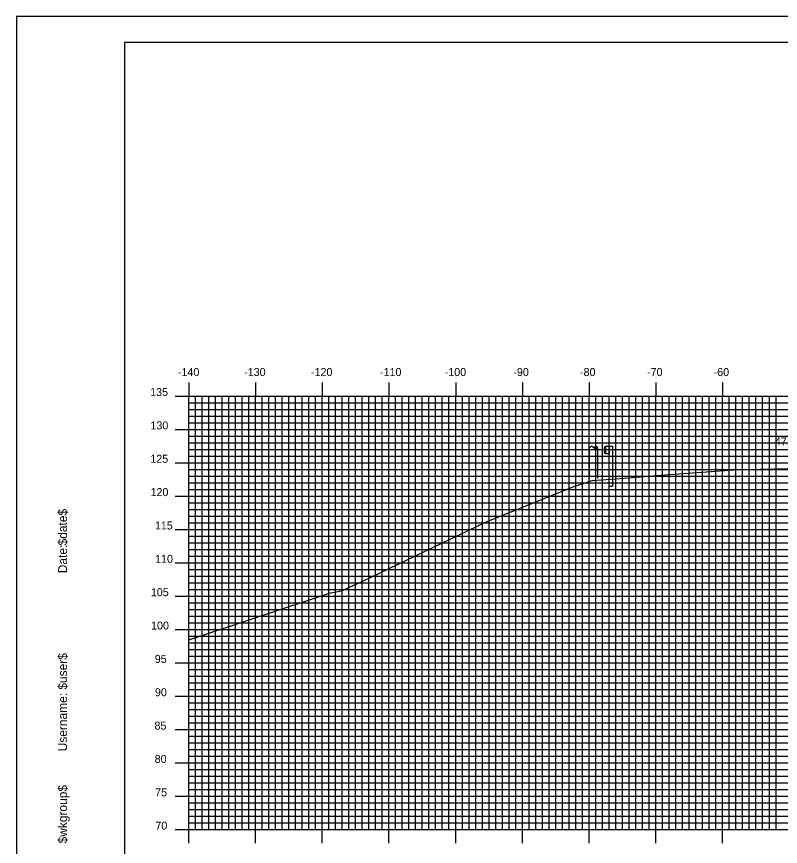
# Model space of a CAD drawing. Extents: x 858684 to 859027, y 364765 to 364985.
# Drawn here: x 858684.1 to 858798.5, y 364860.8 to 364985.2 of the extents above; entities that cross this region are included whole.
import ezdxf

# ---------------------------------------------------------------- set-up
doc = ezdxf.new("R2010")
doc.units = 0
for name, color, linetype in [('BORDER', 7, 'Continuous'), ('D_Text_Standard', 7, 'Continuous'), ('H_V ANNOTATION', 7, 'Continuous'), ('M_Guardrail', 7, 'Continuous'), ('M_Roadway_Centerline', 7, 'Continuous'), ('M_Utilities_Pole_StreetLight', 7, 'Continuous'), ('MAJOR', 7, 'Continuous'), ('MINOR', 7, 'Continuous'), ('PLOT BOUNDARY', 7, 'Continuous'), ('S_Roadway_Centerline', 7, 'Continuous')]:
    doc.layers.add(name, color=color, linetype=linetype)

msp = doc.modelspace()

# ---------------------------------------------------------------- linework, layer by layer
at = {"layer": 'BORDER'}
msp.add_lwpolyline([(858700.25, 364771.3), (859020.25, 364771.3), (859020.25, 364981.3), (858700.25, 364981.3)], close=True, dxfattribs=at)
at = {"layer": 'M_Guardrail'}
for p, q in [((858772.26, 364920.71), (858772.12, 364920.61)), ((858772.12, 364920.47), (858772.31, 364920.33)), ((858772.31, 364920.11), (858772.12, 364919.98)), ((858772.36, 364920.73), (858772.28, 364920.72)), ((858772.34, 364920.27), (858772.34, 364920.18)), ((858772.36, 364920.81), (858772.85, 364920.81)), ((858772.36, 364919.64), (858772.36, 364920.81)), ((858772.85, 364920.81), (858773.34, 364920.81)), ((858772.85, 364920.81), (858772.85, 364919.64)), ((858773.34, 364920.81), (858773.34, 364914.81)), ((858772.12, 364919.83), (858772.26, 364919.73)), ((858772.28, 364919.73), (858772.36, 364919.71)), ((858772.85, 364919.64), (858772.36, 364919.64)), ((858772.85, 364914.81), (858772.85, 364919.64)), ((858772.85, 364914.81), (858773.34, 364914.81))]:
    msp.add_line(p, q, dxfattribs=at)
for centre, major_axis, start_param, end_param in [((858772.17, 364920.54), (-0.0877, 0), 5.323254, 7.243116), ((858772.28, 364920.68), (-0.0417, 0), 4.886922, 5.323254), ((858772.27, 364920.27), (0.0789, 0), 0, 0.959931), ((858772.27, 364920.18), (0.0789, 0), 5.323254, 6.283185), ((858772.17, 364919.91), (-0.0877, 0), 5.323254, 7.243116), ((858772.28, 364919.77), (-0.0417, 0), 0.959931, 1.396263)]:
    msp.add_ellipse(centre, major_axis=major_axis, ratio=0.995501, start_param=start_param, end_param=end_param, dxfattribs=at)
at = {"layer": 'M_Utilities_Pole_StreetLight'}
for p, q in [((858769.9, 364920.59), (858770.06, 364920.7)), ((858769.9, 364915.97), (858769.9, 364920.59)), ((858770.37, 364920.7), (858770.53, 364920.59)), ((858770.68, 364920.7), (858770.53, 364920.59)), ((858770.53, 364920.59), (858770.68, 364920.48)), ((858771.15, 364920.59), (858771, 364920.7)), ((858771, 364920.48), (858771.15, 364920.59)), ((858771.15, 364915.97), (858771.15, 364920.59))]:
    msp.add_line(p, q, dxfattribs=at)
for centre, start, end in [((858770.22, 364920.48), 90, 125.2644), ((858770.22, 364920.48), 54.7356, 90), ((858770.84, 364920.48), 90, 125.2644), ((858770.84, 364920.7), 234.7356, 270), ((858770.84, 364920.48), 54.7356, 90), ((858770.84, 364920.7), 270, 305.2644)]:
    msp.add_arc(centre, 0.271, start, end, dxfattribs=at)
at = {"layer": 'MAJOR'}
for p, q in [((858709.85, 364930.31), (858709.85, 364928.3)), ((858719.85, 364930.31), (858719.85, 364928.3)), ((858729.85, 364930.31), (858729.85, 364928.3)), ((858739.85, 364930.31), (858739.85, 364928.3)), ((858749.85, 364930.31), (858749.85, 364928.3)), ((858759.85, 364930.31), (858759.85, 364928.3)), ((858769.85, 364930.31), (858769.85, 364928.3)), ((858779.85, 364930.31), (858779.85, 364928.3)), ((858789.85, 364930.31), (858789.85, 364928.3)), ((858707.84, 364928.3), (858709.85, 364928.3)), ((858709.85, 364928.3), (858989.85, 364928.3)), ((858709.85, 364863.3), (858709.85, 364928.3)), ((858709.85, 364863.3), (858709.85, 364928.3)), ((858709.85, 364928.3), (858989.85, 364928.3)), ((858719.85, 364863.3), (858719.85, 364928.3)), ((858729.85, 364863.3), (858729.85, 364928.3)), ((858739.85, 364863.3), (858739.85, 364928.3)), ((858749.85, 364863.3), (858749.85, 364928.3)), ((858759.85, 364863.3), (858759.85, 364928.3)), ((858769.85, 364863.3), (858769.85, 364928.3)), ((858779.85, 364863.3), (858779.85, 364928.3)), ((858789.85, 364863.3), (858789.85, 364928.3)), ((858707.84, 364923.3), (858709.85, 364923.3)), ((858709.85, 364923.3), (858989.85, 364923.3)), ((858707.84, 364918.3), (858709.85, 364918.3)), ((858709.85, 364918.3), (858989.85, 364918.3)), ((858707.84, 364913.3), (858709.85, 364913.3)), ((858709.85, 364913.3), (858989.85, 364913.3)), ((858707.84, 364908.3), (858709.85, 364908.3)), ((858709.85, 364908.3), (858989.85, 364908.3)), ((858707.84, 364903.3), (858709.85, 364903.3)), ((858709.85, 364903.3), (858989.85, 364903.3)), ((858707.84, 364898.3), (858709.85, 364898.3)), ((858709.85, 364898.3), (858989.85, 364898.3)), ((858707.84, 364893.3), (858709.85, 364893.3)), ((858709.85, 364893.3), (858989.85, 364893.3)), ((858707.84, 364888.3), (858709.85, 364888.3)), ((858709.85, 364888.3), (858989.85, 364888.3)), ((858707.84, 364883.3), (858709.85, 364883.3)), ((858709.85, 364883.3), (858989.85, 364883.3)), ((858707.84, 364878.3), (858709.85, 364878.3)), ((858709.85, 364878.3), (858989.85, 364878.3)), ((858707.84, 364873.3), (858709.85, 364873.3)), ((858709.85, 364873.3), (858989.85, 364873.3)), ((858707.84, 364868.3), (858709.85, 364868.3)), ((858709.85, 364868.3), (858989.85, 364868.3)), ((858707.84, 364863.3), (858709.85, 364863.3)), ((858709.85, 364863.3), (858989.85, 364863.3)), ((858709.85, 364863.3), (858989.85, 364863.3)), ((858709.85, 364861.3), (858709.85, 364863.3)), ((858719.85, 364861.3), (858719.85, 364863.3)), ((858729.85, 364861.3), (858729.85, 364863.3)), ((858739.85, 364861.3), (858739.85, 364863.3)), ((858749.85, 364861.3), (858749.85, 364863.3)), ((858759.85, 364861.3), (858759.85, 364863.3)), ((858769.85, 364861.3), (858769.85, 364863.3)), ((858779.85, 364861.3), (858779.85, 364863.3)), ((858789.85, 364861.3), (858789.85, 364863.3))]:
    msp.add_line(p, q, dxfattribs=at)
at = {"layer": 'MINOR'}
for p, q in [((858710.85, 364863.3), (858710.85, 364928.3)), ((858711.85, 364863.3), (858711.85, 364928.3)), ((858712.85, 364863.3), (858712.85, 364928.3)), ((858713.85, 364863.3), (858713.85, 364928.3)), ((858714.85, 364863.3), (858714.85, 364928.3)), ((858715.85, 364863.3), (858715.85, 364928.3)), ((858716.85, 364863.3), (858716.85, 364928.3)), ((858717.85, 364863.3), (858717.85, 364928.3)), ((858718.85, 364863.3), (858718.85, 364928.3)), ((858720.85, 364863.3), (858720.85, 364928.3)), ((858721.85, 364863.3), (858721.85, 364928.3)), ((858722.85, 364863.3), (858722.85, 364928.3)), ((858723.85, 364863.3), (858723.85, 364928.3)), ((858724.85, 364863.3), (858724.85, 364928.3)), ((858725.85, 364863.3), (858725.85, 364928.3)), ((858726.85, 364863.3), (858726.85, 364928.3)), ((858727.85, 364863.3), (858727.85, 364928.3)), ((858728.85, 364863.3), (858728.85, 364928.3)), ((858730.85, 364863.3), (858730.85, 364928.3)), ((858731.85, 364863.3), (858731.85, 364928.3)), ((858732.85, 364863.3), (858732.85, 364928.3)), ((858733.85, 364863.3), (858733.85, 364928.3)), ((858734.85, 364863.3), (858734.85, 364928.3)), ((858735.85, 364863.3), (858735.85, 364928.3)), ((858736.85, 364863.3), (858736.85, 364928.3)), ((858737.85, 364863.3), (858737.85, 364928.3)), ((858738.85, 364863.3), (858738.85, 364928.3)), ((858740.85, 364863.3), (858740.85, 364928.3)), ((858741.85, 364863.3), (858741.85, 364928.3)), ((858742.85, 364863.3), (858742.85, 364928.3)), ((858743.85, 364863.3), (858743.85, 364928.3)), ((858744.85, 364863.3), (858744.85, 364928.3)), ((858745.85, 364863.3), (858745.85, 364928.3)), ((858746.85, 364863.3), (858746.85, 364928.3)), ((858747.85, 364863.3), (858747.85, 364928.3)), ((858748.85, 364863.3), (858748.85, 364928.3)), ((858750.85, 364863.3), (858750.85, 364928.3)), ((858751.85, 364863.3), (858751.85, 364928.3)), ((858752.85, 364863.3), (858752.85, 364928.3)), ((858753.85, 364863.3), (858753.85, 364928.3)), ((858754.85, 364863.3), (858754.85, 364928.3)), ((858755.85, 364863.3), (858755.85, 364928.3)), ((858756.85, 364863.3), (858756.85, 364928.3)), ((858757.85, 364863.3), (858757.85, 364928.3)), ((858758.85, 364863.3), (858758.85, 364928.3)), ((858760.85, 364863.3), (858760.85, 364928.3)), ((858761.85, 364863.3), (858761.85, 364928.3)), ((858762.85, 364863.3), (858762.85, 364928.3)), ((858763.85, 364863.3), (858763.85, 364928.3)), ((858764.85, 364863.3), (858764.85, 364928.3)), ((858765.85, 364863.3), (858765.85, 364928.3)), ((858766.85, 364863.3), (858766.85, 364928.3)), ((858767.85, 364863.3), (858767.85, 364928.3)), ((858768.85, 364863.3), (858768.85, 364928.3)), ((858770.85, 364863.3), (858770.85, 364928.3)), ((858771.85, 364863.3), (858771.85, 364928.3)), ((858772.85, 364863.3), (858772.85, 364928.3)), ((858773.85, 364863.3), (858773.85, 364928.3)), ((858774.85, 364863.3), (858774.85, 364928.3)), ((858775.85, 364863.3), (858775.85, 364928.3)), ((858776.85, 364863.3), (858776.85, 364928.3)), ((858777.85, 364863.3), (858777.85, 364928.3)), ((858778.85, 364863.3), (858778.85, 364928.3)), ((858780.85, 364863.3), (858780.85, 364928.3)), ((858781.85, 364863.3), (858781.85, 364928.3)), ((858782.85, 364863.3), (858782.85, 364928.3)), ((858783.85, 364863.3), (858783.85, 364928.3)), ((858784.85, 364863.3), (858784.85, 364928.3)), ((858785.85, 364863.3), (858785.85, 364928.3)), ((858786.85, 364863.3), (858786.85, 364928.3)), ((858787.85, 364863.3), (858787.85, 364928.3)), ((858788.85, 364863.3), (858788.85, 364928.3)), ((858790.85, 364863.3), (858790.85, 364928.3)), ((858791.85, 364863.3), (858791.85, 364928.3)), ((858792.85, 364863.3), (858792.85, 364928.3)), ((858793.85, 364863.3), (858793.85, 364928.3)), ((858794.85, 364863.3), (858794.85, 364928.3)), ((858795.85, 364863.3), (858795.85, 364928.3)), ((858796.85, 364863.3), (858796.85, 364928.3)), ((858797.85, 364863.3), (858797.85, 364928.3)), ((858709.85, 364927.3), (858989.85, 364927.3)), ((858709.85, 364927.3), (858711.85, 364927.3)), ((858709.85, 364926.3), (858989.85, 364926.3)), ((858709.85, 364926.3), (858711.85, 364926.3)), ((858709.85, 364925.3), (858989.85, 364925.3)), ((858709.85, 364925.3), (858711.85, 364925.3)), ((858709.85, 364924.3), (858989.85, 364924.3)), ((858709.85, 364924.3), (858711.85, 364924.3)), ((858709.85, 364922.3), (858989.85, 364922.3)), ((858709.85, 364922.3), (858711.85, 364922.3)), ((858709.85, 364921.3), (858989.85, 364921.3)), ((858709.85, 364921.3), (858711.85, 364921.3)), ((858709.85, 364920.3), (858989.85, 364920.3)), ((858709.85, 364920.3), (858711.85, 364920.3)), ((858709.85, 364919.3), (858989.85, 364919.3)), ((858709.85, 364919.3), (858711.85, 364919.3)), ((858709.85, 364917.3), (858989.85, 364917.3)), ((858709.85, 364917.3), (858711.85, 364917.3)), ((858709.85, 364916.3), (858989.85, 364916.3)), ((858709.85, 364916.3), (858711.85, 364916.3)), ((858709.85, 364915.3), (858989.85, 364915.3)), ((858709.85, 364915.3), (858711.85, 364915.3)), ((858709.85, 364914.3), (858989.85, 364914.3)), ((858709.85, 364914.3), (858711.85, 364914.3)), ((858709.85, 364912.3), (858989.85, 364912.3)), ((858709.85, 364912.3), (858711.85, 364912.3)), ((858709.85, 364911.3), (858989.85, 364911.3)), ((858709.85, 364911.3), (858711.85, 364911.3)), ((858709.85, 364910.3), (858989.85, 364910.3)), ((858709.85, 364910.3), (858711.85, 364910.3)), ((858709.85, 364909.3), (858989.85, 364909.3)), ((858709.85, 364909.3), (858711.85, 364909.3)), ((858709.85, 364907.3), (858989.85, 364907.3)), ((858709.85, 364907.3), (858711.85, 364907.3)), ((858709.85, 364906.3), (858989.85, 364906.3)), ((858709.85, 364906.3), (858711.85, 364906.3)), ((858709.85, 364905.3), (858989.85, 364905.3)), ((858709.85, 364905.3), (858711.85, 364905.3)), ((858709.85, 364904.3), (858989.85, 364904.3)), ((858709.85, 364904.3), (858711.85, 364904.3)), ((858709.85, 364902.3), (858989.85, 364902.3)), ((858709.85, 364902.3), (858711.85, 364902.3)), ((858709.85, 364901.3), (858989.85, 364901.3)), ((858709.85, 364901.3), (858711.85, 364901.3)), ((858709.85, 364900.3), (858989.85, 364900.3)), ((858709.85, 364900.3), (858711.85, 364900.3)), ((858709.85, 364899.3), (858989.85, 364899.3)), ((858709.85, 364899.3), (858711.85, 364899.3)), ((858709.85, 364897.3), (858989.85, 364897.3)), ((858709.85, 364897.3), (858711.85, 364897.3)), ((858709.85, 364896.3), (858989.85, 364896.3)), ((858709.85, 364896.3), (858711.85, 364896.3)), ((858709.85, 364895.3), (858989.85, 364895.3)), ((858709.85, 364895.3), (858711.85, 364895.3)), ((858709.85, 364894.3), (858989.85, 364894.3)), ((858709.85, 364894.3), (858711.85, 364894.3)), ((858709.85, 364892.3), (858989.85, 364892.3)), ((858709.85, 364892.3), (858711.85, 364892.3)), ((858709.85, 364891.3), (858989.85, 364891.3)), ((858709.85, 364891.3), (858711.85, 364891.3)), ((858709.85, 364890.3), (858989.85, 364890.3)), ((858709.85, 364890.3), (858711.85, 364890.3)), ((858709.85, 364889.3), (858989.85, 364889.3)), ((858709.85, 364889.3), (858711.85, 364889.3)), ((858709.85, 364887.3), (858989.85, 364887.3)), ((858709.85, 364887.3), (858711.85, 364887.3)), ((858709.85, 364886.3), (858989.85, 364886.3)), ((858709.85, 364886.3), (858711.85, 364886.3)), ((858709.85, 364885.3), (858989.85, 364885.3)), ((858709.85, 364885.3), (858711.85, 364885.3)), ((858709.85, 364884.3), (858989.85, 364884.3)), ((858709.85, 364884.3), (858711.85, 364884.3)), ((858709.85, 364882.3), (858989.85, 364882.3)), ((858709.85, 364882.3), (858711.85, 364882.3)), ((858709.85, 364881.3), (858989.85, 364881.3)), ((858709.85, 364881.3), (858711.85, 364881.3)), ((858709.85, 364880.3), (858989.85, 364880.3)), ((858709.85, 364880.3), (858711.85, 364880.3)), ((858709.85, 364879.3), (858989.85, 364879.3)), ((858709.85, 364879.3), (858711.85, 364879.3)), ((858709.85, 364877.3), (858989.85, 364877.3)), ((858709.85, 364877.3), (858711.85, 364877.3)), ((858709.85, 364876.3), (858989.85, 364876.3)), ((858709.85, 364876.3), (858711.85, 364876.3)), ((858709.85, 364875.3), (858989.85, 364875.3)), ((858709.85, 364875.3), (858711.85, 364875.3)), ((858709.85, 364874.3), (858989.85, 364874.3)), ((858709.85, 364874.3), (858711.85, 364874.3)), ((858709.85, 364872.3), (858989.85, 364872.3)), ((858709.85, 364872.3), (858711.85, 364872.3)), ((858709.85, 364871.3), (858989.85, 364871.3)), ((858709.85, 364871.3), (858711.85, 364871.3)), ((858709.85, 364870.3), (858989.85, 364870.3)), ((858709.85, 364870.3), (858711.85, 364870.3)), ((858709.85, 364869.3), (858989.85, 364869.3)), ((858709.85, 364869.3), (858711.85, 364869.3)), ((858709.85, 364867.3), (858989.85, 364867.3)), ((858709.85, 364867.3), (858711.85, 364867.3)), ((858709.85, 364866.3), (858989.85, 364866.3)), ((858709.85, 364866.3), (858711.85, 364866.3)), ((858709.85, 364865.3), (858989.85, 364865.3)), ((858709.85, 364865.3), (858711.85, 364865.3)), ((858709.85, 364864.3), (858989.85, 364864.3)), ((858709.85, 364864.3), (858711.85, 364864.3))]:
    msp.add_line(p, q, dxfattribs=at)
at = {"layer": 'PLOT BOUNDARY'}
msp.add_lwpolyline([(858684.06, 364765.18), (859024.06, 364765.18), (859024.06, 364985.18), (858684.06, 364985.18)], close=True, dxfattribs=at)
at = {"layer": 'S_Roadway_Centerline'}
msp.add_lwpolyline([(858709.85, 364891.74), (858709.89, 364891.74), (858731.11, 364898.79), (858732.77, 364899.1), (858734.05, 364899.72), (858735.92, 364900.56), (858754.3, 364909.41), (858767.3, 364914.63), (858770.31, 364915.64), (858774.46, 364915.95), (858781.18, 364916.47), (858790.89, 364917.21), (858791.18, 364917.22), (858791.46, 364917.22), (858801.59, 364917.48)], dxfattribs=at)

# ---------------------------------------------------------------- texts
at = {"layer": 'BORDER'}
for s, p in [('$date$', (858691.62, 364905.91)), ('Date:', (858691.62, 364901.74)), ('$user$', (858691.62, 364884.29)), ('Username:', (858691.62, 364875.04)), ('$wkgroup$', (858691.62, 364861.24))]:
    msp.add_text(s, height=1.339, rotation=90, dxfattribs=at).set_placement(p)
at = {"layer": 'D_Text_Standard'}
msp.add_text("47.6'", height=1.2, dxfattribs=at).set_placement((858797.67, 364920.91))
at = {"layer": 'H_V ANNOTATION'}
for s, p in [('-140', (858708.23, 364931.3)), ('-130', (858718.16, 364931.3)), ('-120', (858728.17, 364931.3)), ('-110', (858738.51, 364931.3)), ('-100', (858748.21, 364931.3)), ('-90', (858758.5, 364931.3)), ('-80', (858768.48, 364931.3)), ('-70', (858778.53, 364931.3)), ('-60', (858788.5, 364931.3)), ('135', (858704.07, 364928.3)), ('130', (858704.11, 364923.3)), ('125', (858704.1, 364918.3)), ('120', (858704.13, 364913.3)), ('115', (858704.78, 364908.3)), ('110', (858704.81, 364903.3)), ('105', (858704.18, 364898.3)), ('100', (858704.21, 364893.3)), ('95', (858704.76, 364888.3)), ('90', (858704.79, 364883.3)), ('85', (858704.72, 364878.3)), ('80', (858704.75, 364873.3)), ('75', (858704.82, 364868.3)), ('70', (858704.86, 364863.3))]:
    msp.add_text(s, height=1.2, dxfattribs=at).set_placement(p)
at = {"layer": 'M_Roadway_Centerline'}
for s, p in [('C', (858790.89, 364917.21)), ('L', (858790.89, 364917.2))]:
    msp.add_text(s, height=0.0146, dxfattribs=at).set_placement(p)
at = {"layer": 'MAJOR'}
msp.add_text('-', height=0.012, dxfattribs=at).set_placement((858709.84, 364863.3))

doc.saveas('drawing.dxf')
